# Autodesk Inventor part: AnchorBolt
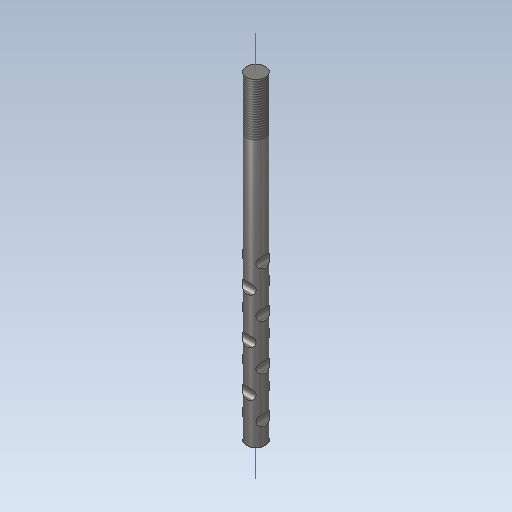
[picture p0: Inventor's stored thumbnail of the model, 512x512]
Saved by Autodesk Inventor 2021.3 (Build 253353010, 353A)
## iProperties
Created: 2019-05
Part Number: AnchorBolt
Material: Steel, Galvanized
Document SubType Name: Modeling
Designer: u1426
Density: 7.85 g/cm^3
Appearance: Galvanized
Protrusion: 6.000 in
BoltDiameter: 1.250 in
EmbedConcrete: 15.000 in
NoSwedgesLeast: 3.000 ul
Author: u1426
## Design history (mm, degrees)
sketch "Sketch1"
  geometry: C1 r 15.875 at (0, 0); 1 further point
  constraints: 1 centre point, 1 coincident, 1 other
extrude "Extrusion1" new body sketch "Sketch1" taper "d3" = 0 deg; dims "d4" = 0
thread "Thread1" dims "d5" = 88.9 (derived), "d6" = 0
sketch "Sketch4"
  geometry: L1 (152.4, 15.875)-(-381, 15.875) reference; L2 (152.4, 15.875)-(-381, 15.875) reference; L3 (-295.275, 15.875)-(-314.325, 15.875); L4 (165.1, 19.05)-(-381, 19.05); L5 (165.1, 19.05)-(-381, 19.05); L6 (165.1, 19.05)-(-381, 19.05); L7 (165.1, 19.05)-(-381, 19.05); A1 r 11.906 centre (-304.8, 23.019) between (-314.325, 15.875) and (-295.275, 15.875); 11 further points
  constraints: 10 end point, 2 point on circle, 1 centre point, 6 other
  dimensions: "d29" = 19.05 distance of L3.start L3.end; "d30" = 11.90625 radius of A1; "d31" = 76.2 horizontal distance of A1.centre L1.end; "d32" = 9.525 horizontal distance of L3.end A1.centre
extrude "Extrusion2" cut sketch "Sketch4" extent not by distance; stored distance "d9" = 25.4; taper "d10" = 0 deg
mirror "Mirror1"
pattern_linear "Rectangular Pattern1" dims "d39" = 76.2
sketch "Sketch6"
  geometry: L1 (-381, 15.875)-(-381, -15.875) reference; L2 (152.4, 15.875)-(-381, 15.875) reference; L3 (-333.375, 15.875)-(-352.425, 15.875); A1 r 11.906 centre (-342.9, 23.019) between (-352.425, 15.875) and (-333.375, 15.875); 1 further point
  constraints: 2 end point, 2 point on circle, 2 point on line, 1 centre point, 1 horizontal
  dimensions: "d46" = 19.05 distance of L3.end L3.start; "d48" = 38.1 horizontal distance of A1.centre L2.end; "d49" = 11.90625 radius of A1
extrude "Extrusion4" cut sketch "Sketch6" extent not by distance; stored distance "d44" = 25.4; taper "d45" = 0 deg
mirror "Mirror2"
pattern_linear "Rectangular Pattern3" dims "d55" = 76.2
body "Solid1"
workaxis "Work Axis5"
workaxis "Work Axis36"
